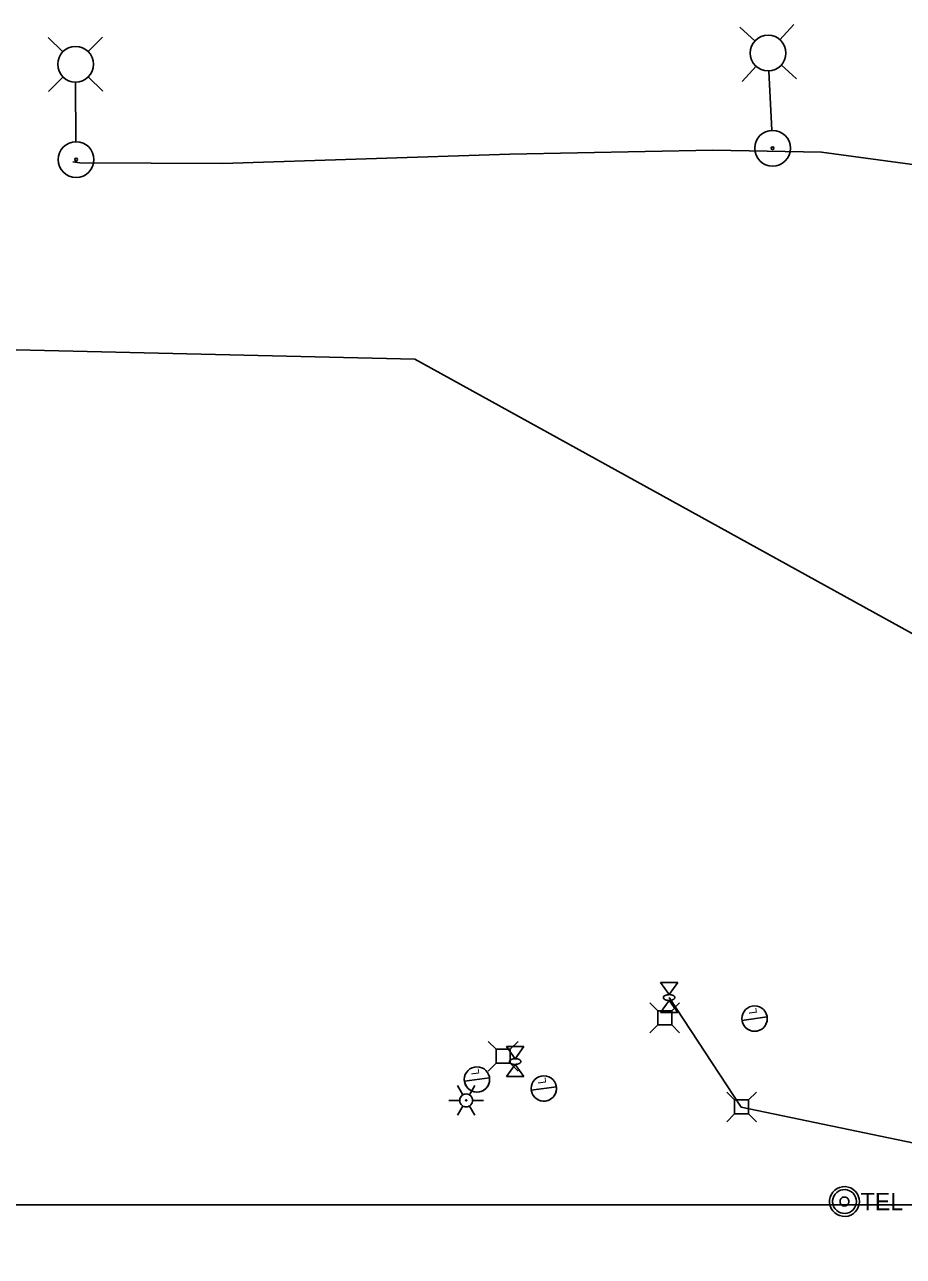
# Model space of a CAD drawing. Extents: x 596028 to 606371, y 330010 to 403088.
# Drawn here: x 603285.2 to 603479.7, y 349658.5 to 349931.1 of the extents above; entities that cross this region are included whole.
import ezdxf

# ---------------------------------------------------------------- set-up
doc = ezdxf.new("R2010")
doc.units = 0
for name, color, linetype in [('E_LTG', 7, 'Continuous'), ('E_LTG_CID', 7, 'Continuous'), ('E_UTL_E', 7, 'Continuous'), ('E_UTL_E_Bold', 7, 'Continuous'), ('E_UTL_E_UG', 7, 'Continuous'), ('E_UTL_T_MH', 7, 'Continuous'), ('E_UTL_T_UG', 7, 'Continuous')]:
    doc.layers.add(name, color=color, linetype=linetype)

# ---------------------------------------------------------------- blocks, each defined once
blk = doc.blocks.new('ACAD_PROXY_ENTITY_15')
at = {"layer": 'E_LTG'}
for points in [[(1843663.8, 1030159.59), (1843660.17, 1030165.87)], [(1843668.16, 1030159.59), (1843671.79, 1030165.87)], [(1843654.37, 1030155.82), (1843661.62, 1030155.82)], [(1843670.34, 1030155.82), (1843670.26, 1030156.64), (1843670.02, 1030157.44), (1843669.64, 1030158.17), (1843669.13, 1030158.82), (1843668.51, 1030159.36), (1843667.79, 1030159.78), (1843667.01, 1030160.05), (1843666.19, 1030160.17), (1843665.36, 1030160.13), (1843664.56, 1030159.93), (1843663.8, 1030159.59), (1843663.13, 1030159.11), (1843662.56, 1030158.51), (1843662.11, 1030157.81), (1843661.8, 1030157.04), (1843661.64, 1030156.23), (1843661.64, 1030155.4), (1843661.8, 1030154.59), (1843662.11, 1030153.82), (1843662.56, 1030153.12), (1843663.13, 1030152.52), (1843663.8, 1030152.04), (1843664.56, 1030151.7), (1843665.36, 1030151.51), (1843666.19, 1030151.47), (1843667.01, 1030151.58), (1843667.79, 1030151.85), (1843668.51, 1030152.27), (1843669.13, 1030152.81), (1843669.64, 1030153.46), (1843670.02, 1030154.2), (1843670.26, 1030154.99), (1843670.34, 1030155.82)], [(1843670.34, 1030155.82), (1843670.26, 1030156.64), (1843670.02, 1030157.44), (1843669.64, 1030158.17), (1843669.13, 1030158.82), (1843668.51, 1030159.36), (1843667.79, 1030159.78), (1843667.01, 1030160.05), (1843666.19, 1030160.17), (1843665.36, 1030160.13), (1843664.56, 1030159.93), (1843663.8, 1030159.59), (1843663.13, 1030159.11), (1843662.56, 1030158.51), (1843662.11, 1030157.81), (1843661.8, 1030157.04), (1843661.64, 1030156.23), (1843661.64, 1030155.4), (1843661.8, 1030154.59), (1843662.11, 1030153.82), (1843662.56, 1030153.12), (1843663.13, 1030152.52), (1843663.8, 1030152.04), (1843664.56, 1030151.7), (1843665.36, 1030151.51), (1843666.19, 1030151.47), (1843667.01, 1030151.58), (1843667.79, 1030151.85), (1843668.51, 1030152.27), (1843669.13, 1030152.81), (1843669.64, 1030153.46), (1843670.02, 1030154.2), (1843670.26, 1030154.99), (1843670.34, 1030155.82)], [(1843670.34, 1030155.82), (1843670.26, 1030156.64), (1843670.02, 1030157.44), (1843669.64, 1030158.17), (1843669.13, 1030158.82), (1843668.51, 1030159.36), (1843667.79, 1030159.78), (1843667.01, 1030160.05), (1843666.19, 1030160.17), (1843665.36, 1030160.13), (1843664.56, 1030159.93), (1843663.8, 1030159.59), (1843663.13, 1030159.11), (1843662.56, 1030158.51), (1843662.11, 1030157.81), (1843661.8, 1030157.04), (1843661.64, 1030156.23), (1843661.64, 1030155.4), (1843661.8, 1030154.59), (1843662.11, 1030153.82), (1843662.56, 1030153.12), (1843663.13, 1030152.52), (1843663.8, 1030152.04), (1843664.56, 1030151.7), (1843665.36, 1030151.51), (1843666.19, 1030151.47), (1843667.01, 1030151.58), (1843667.79, 1030151.85), (1843668.51, 1030152.27), (1843669.13, 1030152.81), (1843669.64, 1030153.46), (1843670.02, 1030154.2), (1843670.26, 1030154.99), (1843670.34, 1030155.82)], [(1843666.34, 1030155.82), (1843666.34, 1030155.88), (1843666.32, 1030155.95), (1843666.29, 1030156.01), (1843666.24, 1030156.07), (1843666.19, 1030156.11), (1843666.13, 1030156.15), (1843666.07, 1030156.17), (1843666, 1030156.18), (1843665.93, 1030156.18), (1843665.86, 1030156.16), (1843665.8, 1030156.13), (1843665.74, 1030156.09), (1843665.69, 1030156.04), (1843665.66, 1030155.98), (1843665.63, 1030155.92), (1843665.62, 1030155.85), (1843665.62, 1030155.78), (1843665.63, 1030155.71), (1843665.66, 1030155.65), (1843665.69, 1030155.59), (1843665.74, 1030155.54), (1843665.8, 1030155.5), (1843665.86, 1030155.47), (1843665.93, 1030155.46), (1843666, 1030155.45), (1843666.07, 1030155.46), (1843666.13, 1030155.49), (1843666.19, 1030155.52), (1843666.24, 1030155.57), (1843666.29, 1030155.62), (1843666.32, 1030155.68), (1843666.34, 1030155.75), (1843666.34, 1030155.82)], [(1843670.34, 1030155.82), (1843677.59, 1030155.82)], [(1843660.17, 1030145.76), (1843663.8, 1030152.04)], [(1843671.79, 1030145.76), (1843668.16, 1030152.04)]]:
    blk.add_lwpolyline(points, dxfattribs=at)
blk = doc.blocks.new('_U272')
at = {"layer": 'E_LTG'}
blk.add_lwpolyline([(0.001, -0.171), (0.001, 0.172)], dxfattribs=at)
blk.add_circle((0.001, 0), 0.171, dxfattribs=at)
blk.add_arc((0.001, 0), 0.171, 90, 270, dxfattribs=at)
blk.add_text('L', height=0.108, dxfattribs=at).set_placement((0.066, -0.042))

msp = doc.modelspace()

# ---------------------------------------------------------------- linework, layer by layer
at = {"layer": 'E_LTG'}
for points in [[(603446.88, 349927.43), (603443.5, 349930.5)], [(603452.41, 349927.69), (603455.49, 349931.07)], [(603293.67, 349925.05), (603290.43, 349928.26)], [(603299.21, 349925.08), (603302.43, 349928.33)], [(603452.67, 349922.16), (603456.05, 349919.08)], [(603293.7, 349919.51), (603290.49, 349916.26)], [(603299.24, 349919.54), (603302.49, 349916.33)], [(603447.14, 349921.9), (603444.07, 349918.51)], [(603449.97, 349920.77), (603450.59, 349907.74)], [(603296.48, 349918.27), (603296.55, 349905.22)]]:
    msp.add_lwpolyline(points, dxfattribs=at)
for centre, radius in [((603449.78, 349924.79), 3.96), ((603296.46, 349922.29), 3.96), ((603450.78, 349903.72), 3.96), ((603296.58, 349901.2), 3.96), ((603450.78, 349903.72), 0.303), ((603296.58, 349901.2), 0.303)]:
    msp.add_circle(centre, radius, dxfattribs=at)
at = {"layer": 'E_LTG_CID'}
msp.add_lwpolyline([(603488.28, 349899.27), (603461.6, 349902.84), (603437.56, 349903.33), (603392.61, 349902.38), (603328.99, 349900.36), (603297.43, 349900.48), (603295.89, 349900.75)], dxfattribs=at)
at = {"layer": 'E_UTL_E'}
for points in [[(603425.35, 349712.84), (603423.6, 349714.59)], [(603428.45, 349712.84), (603425.35, 349712.84)], [(603425.35, 349712.84), (603425.35, 349709.74)], [(603428.45, 349712.84), (603430.2, 349714.59)], [(603428.45, 349709.74), (603428.45, 349712.84)], [(603425.35, 349709.74), (603423.6, 349707.99)], [(603425.35, 349709.74), (603428.45, 349709.74)], [(603428.45, 349709.74), (603430.2, 349707.99)], [(603389.57, 349704.35), (603387.81, 349706.1)], [(603392.66, 349704.35), (603389.57, 349704.35)], [(603389.57, 349704.35), (603389.57, 349701.25)], [(603392.66, 349704.35), (603394.41, 349706.1)], [(603392.66, 349701.25), (603392.66, 349704.35)], [(603389.57, 349701.25), (603387.81, 349699.5)], [(603389.57, 349701.25), (603392.66, 349701.25)], [(603392.66, 349701.25), (603394.41, 349699.5)], [(603442.36, 349693.13), (603440.61, 349694.88)], [(603445.45, 349693.13), (603442.36, 349693.13)], [(603442.36, 349693.13), (603442.36, 349690.03)], [(603445.45, 349693.13), (603447.21, 349694.88)], [(603445.45, 349690.03), (603445.45, 349693.13)], [(603442.36, 349690.03), (603440.61, 349688.28)], [(603442.36, 349690.03), (603445.45, 349690.03)], [(603445.45, 349690.03), (603447.21, 349688.28)]]:
    msp.add_lwpolyline(points, dxfattribs=at)
at = {"layer": 'E_UTL_E_Bold'}
for points in [[(603425.94, 349719.1), (603429.76, 349719.1)], [(603427.85, 349716.44), (603425.94, 349719.1)], [(603429.76, 349719.1), (603427.85, 349716.44)], [(603427.85, 349715.17), (603425.94, 349712.5)], [(603429.12, 349715.8), (603429.1, 349715.92), (603429.03, 349716.04), (603428.92, 349716.15), (603428.77, 349716.24), (603428.59, 349716.32), (603428.38, 349716.38), (603428.15, 349716.42), (603427.91, 349716.44), (603427.67, 349716.43), (603427.43, 349716.4), (603427.21, 349716.35), (603427.02, 349716.28), (603426.85, 349716.2), (603426.72, 349716.09), (603426.63, 349715.98), (603426.59, 349715.86), (603426.59, 349715.74), (603426.63, 349715.62), (603426.72, 349715.51), (603426.85, 349715.41), (603427.02, 349715.32), (603427.21, 349715.25), (603427.43, 349715.2), (603427.67, 349715.17), (603427.91, 349715.17), (603428.15, 349715.19), (603428.38, 349715.23), (603428.59, 349715.29), (603428.77, 349715.36), (603428.92, 349715.46), (603429.03, 349715.57), (603429.1, 349715.68), (603429.12, 349715.8)], [(603429.76, 349712.5), (603427.85, 349715.17)], [(603425.94, 349712.5), (603429.76, 349712.5)], [(603391.88, 349704.93), (603395.69, 349704.93)], [(603393.78, 349702.27), (603391.88, 349704.93)], [(603395.69, 349704.93), (603393.78, 349702.27)], [(603395.05, 349701.64), (603395.03, 349701.76), (603394.96, 349701.87), (603394.85, 349701.98), (603394.7, 349702.07), (603394.52, 349702.15), (603394.31, 349702.21), (603394.08, 349702.25), (603393.84, 349702.27), (603393.6, 349702.26), (603393.37, 349702.24), (603393.15, 349702.19), (603392.95, 349702.11), (603392.78, 349702.03), (603392.65, 349701.93), (603392.56, 349701.81), (603392.52, 349701.7), (603392.52, 349701.57), (603392.56, 349701.46), (603392.65, 349701.34), (603392.78, 349701.24), (603392.95, 349701.16), (603393.15, 349701.08), (603393.37, 349701.03), (603393.6, 349701.01), (603393.84, 349701), (603394.08, 349701.02), (603394.31, 349701.06), (603394.52, 349701.12), (603394.7, 349701.2), (603394.85, 349701.29), (603394.96, 349701.4), (603395.03, 349701.51), (603395.05, 349701.64)], [(603393.78, 349701), (603391.88, 349698.34)], [(603395.69, 349698.34), (603393.78, 349701)], [(603391.88, 349698.34), (603395.69, 349698.34)]]:
    msp.add_lwpolyline(points, dxfattribs=at)
at = {"layer": 'E_UTL_E_UG'}
msp.add_lwpolyline([(603427.85, 349715.8), (603443.8, 349691.57), (603602.35, 349658.56), (603623.55, 349660.03)], dxfattribs=at)
at = {"layer": 'E_UTL_T_MH'}
for points in [[(603469.99, 349670.66), (603469.93, 349671.29), (603469.75, 349671.89), (603469.46, 349672.45), (603469.08, 349672.94), (603468.6, 349673.35), (603468.06, 349673.66), (603467.47, 349673.87), (603466.84, 349673.96), (603466.22, 349673.93), (603465.61, 349673.78), (603465.04, 349673.52), (603464.53, 349673.16), (603464.09, 349672.7), (603463.75, 349672.17), (603463.52, 349671.59), (603463.4, 349670.98), (603463.4, 349670.35), (603463.52, 349669.73), (603463.75, 349669.15), (603464.09, 349668.62), (603464.53, 349668.17), (603465.04, 349667.8), (603465.61, 349667.54), (603466.22, 349667.4), (603466.84, 349667.37), (603467.47, 349667.45), (603468.06, 349667.66), (603468.6, 349667.97), (603469.08, 349668.38), (603469.46, 349668.88), (603469.75, 349669.44), (603469.93, 349670.04), (603469.99, 349670.66)], [(603469.33, 349670.66), (603469.28, 349671.16), (603469.14, 349671.64), (603468.91, 349672.09), (603468.6, 349672.48), (603468.22, 349672.81), (603467.78, 349673.06), (603467.31, 349673.23), (603466.81, 349673.3), (603466.31, 349673.27), (603465.82, 349673.16), (603465.37, 349672.95), (603464.96, 349672.66), (603464.61, 349672.29), (603464.34, 349671.87), (603464.15, 349671.41), (603464.06, 349670.91), (603464.06, 349670.41), (603464.15, 349669.92), (603464.34, 349669.45), (603464.61, 349669.03), (603464.96, 349668.67), (603465.37, 349668.38), (603465.82, 349668.17), (603466.31, 349668.05), (603466.81, 349668.02), (603467.31, 349668.1), (603467.78, 349668.26), (603468.22, 349668.51), (603468.6, 349668.84), (603468.91, 349669.23), (603469.14, 349669.68), (603469.28, 349670.16), (603469.33, 349670.66)], [(603467.68, 349670.66), (603467.66, 349670.85), (603467.61, 349671.03), (603467.52, 349671.2), (603467.4, 349671.35), (603467.26, 349671.47), (603467.1, 349671.56), (603466.92, 349671.62), (603466.73, 349671.65), (603466.55, 349671.64), (603466.36, 349671.6), (603466.19, 349671.52), (603466.04, 349671.41), (603465.91, 349671.27), (603465.81, 349671.12), (603465.74, 349670.94), (603465.7, 349670.76), (603465.7, 349670.57), (603465.74, 349670.38), (603465.81, 349670.21), (603465.91, 349670.05), (603466.04, 349669.91), (603466.19, 349669.8), (603466.36, 349669.73), (603466.55, 349669.68), (603466.73, 349669.67), (603466.92, 349669.7), (603467.1, 349669.76), (603467.26, 349669.86), (603467.4, 349669.98), (603467.52, 349670.13), (603467.61, 349670.29), (603467.66, 349670.47), (603467.68, 349670.66)]]:
    msp.add_lwpolyline(points, dxfattribs=at)
at = {"layer": 'E_UTL_T_UG'}
for points in [[(603184.3, 349870.93), (603185.43, 349861.41), (603371.56, 349857.02), (603580.78, 349741.72), (603627.61, 349658.53)], [(603240.83, 349669.94), (603639.16, 349669.94)]]:
    msp.add_lwpolyline(points, dxfattribs=at)

# ---------------------------------------------------------------- block references
at = {"layer": 'E_LTG', "xscale": 0.32808333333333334, "yscale": 0.32808333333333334}
msp.add_blockref('ACAD_PROXY_ENTITY_15', (-1493.15, 11716.08), dxfattribs=at)
at = {"layer": 'E_LTG_CID', "xscale": 16.404166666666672, "yscale": 16.404166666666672, "rotation": 97.82095686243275}
for p in [(603446.79, 349711.12), (603385.33, 349697.66), (603400.13, 349695.66)]:
    msp.add_blockref('_U272', p, dxfattribs=at)

# ---------------------------------------------------------------- texts
at = {"layer": 'E_UTL_T_MH'}
msp.add_text('TEL', height=3.849, dxfattribs=at).set_placement((603470.25, 349668.72))

doc.saveas('drawing.dxf')
